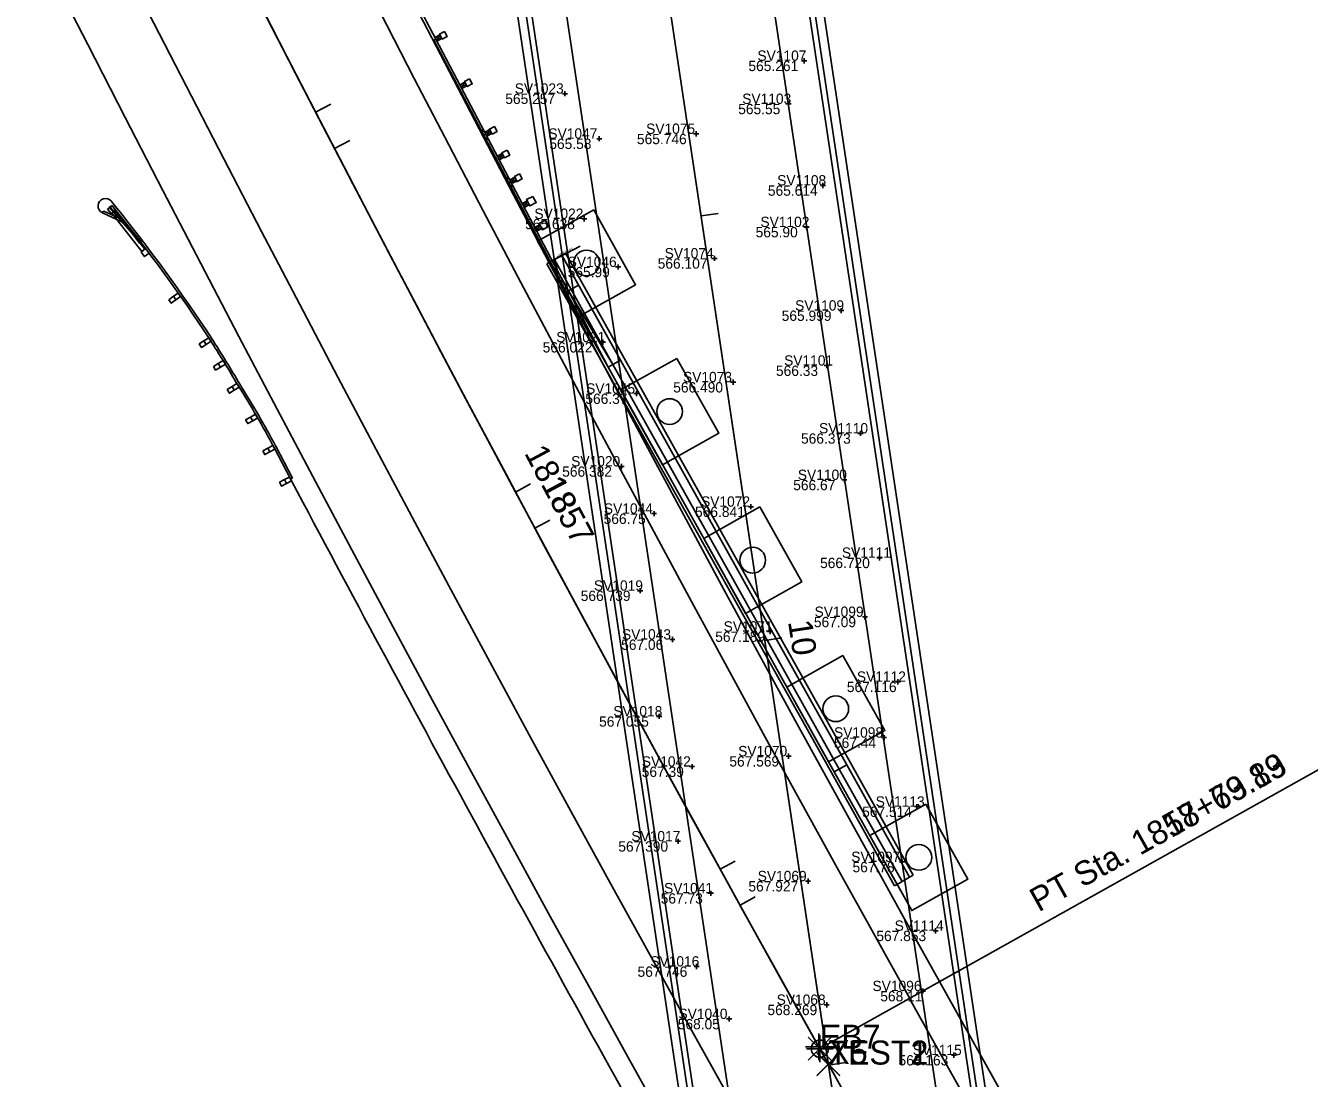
# Model space of a CAD drawing. Extents: x 6334 to 41599, y 9030 to 59113.
# Drawn here: x 21027.9 to 21177.4, y 34361.6 to 34484.2 of the extents above; entities that cross this region are included whole.
import ezdxf

# ---------------------------------------------------------------- set-up
doc = ezdxf.new("R2010")
doc.units = 0
for name, color, linetype in [('BR_X_Slab_Centerline', 7, 'Continuous'), ('BR_X_SV_Deck_Top', 7, 'Continuous'), ('BR_X_SV_Deck_Top_Text', 7, 'Continuous'), ('BR_X_SV_Pier', 7, 'Continuous'), ('GE_P_CL_20', 7, 'Continuous'), ('GE_X_CL_20', 7, 'Continuous'), ('GK_Visualization', 7, 'Continuous'), ('PM_X_CL_Double_Solid', 7, 'Continuous'), ('PM_X_Lane_Line', 7, 'Continuous'), ('PV_X_EOP', 7, 'Continuous'), ('PV_X_Shoulder', 7, 'Continuous'), ('RD_P_Concrete_Barrier', 7, 'Continuous'), ('RD_P_GR_Lt_Replaced', 7, 'Continuous'), ('RD_P_GR_Rt_Replaced', 7, 'Continuous'), ('SV_X_Shot_Marker', 7, 'Continuous'), ('SV_X_Text_Elevation', 7, 'Continuous'), ('SV_X_Text_Name', 7, 'Continuous')]:
    doc.layers.add(name, color=color, linetype=linetype)

msp = doc.modelspace()

# ---------------------------------------------------------------- linework, layer by layer
at = {"layer": 'BR_X_Slab_Centerline'}
msp.add_line((21088.12, 34584.84), (21156.74, 34127.95), dxfattribs=at)
at = {"layer": 'BR_X_SV_Deck_Top'}
for p, q in [((21072.33, 34570.99), (21124.14, 34226.08)), ((21073.52, 34569.83), (21125.21, 34225.67)), ((21074.44, 34568.18), (21126.13, 34224.03)), ((21118.68, 34489.07), (21170.37, 34144.92)), ((21119.6, 34487.43), (21171.29, 34143.27)), ((21120.67, 34487.02), (21172.48, 34142.11))]:
    msp.add_line(p, q, dxfattribs=at)
at = {"layer": 'BR_X_SV_Deck_Top_Text'}
for p, q in [((21118.87, 34480.12), (21118.27, 34480.12)), ((21118.57, 34480.42), (21118.57, 34479.82)), ((21090.7, 34476.59), (21090.7, 34475.99)), ((21091, 34476.29), (21090.4, 34476.29)), ((21120.77, 34465.9), (21120.77, 34465.3)), ((21121.07, 34465.6), (21120.47, 34465.6)), ((21093.26, 34461.71), (21092.66, 34461.71)), ((21092.96, 34462.01), (21092.96, 34461.41)), ((21123.2, 34451.03), (21122.6, 34451.03)), ((21122.9, 34451.33), (21122.9, 34450.73)), ((21095.41, 34447.35), (21094.81, 34447.35)), ((21095.11, 34447.65), (21095.11, 34447.05)), ((21125.44, 34436.73), (21124.84, 34436.73)), ((21125.14, 34437.03), (21125.14, 34436.43)), ((21097.3, 34433.18), (21097.3, 34432.58)), ((21097.6, 34432.88), (21097, 34432.88)), ((21127.35, 34422.54), (21127.35, 34421.94)), ((21127.65, 34422.24), (21127.05, 34422.24)), ((21099.76, 34418.41), (21099.16, 34418.41)), ((21099.46, 34418.71), (21099.46, 34418.11)), ((21129.8, 34407.8), (21129.2, 34407.8)), ((21129.5, 34408.1), (21129.5, 34407.5)), ((21101.98, 34403.77), (21101.38, 34403.77)), ((21101.68, 34404.07), (21101.68, 34403.47)), ((21132.02, 34393.26), (21131.42, 34393.26)), ((21131.72, 34393.56), (21131.72, 34392.96)), ((21104.18, 34389.22), (21103.58, 34389.22)), ((21103.88, 34389.52), (21103.88, 34388.92)), ((21134.19, 34378.8), (21133.59, 34378.8)), ((21133.89, 34379.1), (21133.89, 34378.5)), ((21106.34, 34374.64), (21105.74, 34374.64)), ((21106.04, 34374.94), (21106.04, 34374.34)), ((21136.33, 34364.32), (21135.73, 34364.32)), ((21136.03, 34364.62), (21136.03, 34364.02))]:
    msp.add_line(p, q, dxfattribs=at)
at = {"layer": 'BR_X_SV_Pier'}
for points in [[(21094.06, 34462.77), (21098.94, 34454.04), (21092.39, 34450.38), (21087.51, 34459.11)], [(21103.73, 34445.46), (21108.62, 34436.74), (21102.07, 34433.07), (21097.19, 34441.8)], [(21113.41, 34428.16), (21118.29, 34419.43), (21111.75, 34415.77), (21106.87, 34424.5)], [(21123.09, 34410.85), (21127.97, 34402.12), (21121.43, 34398.46), (21116.55, 34407.19)], [(21132.77, 34393.55), (21137.65, 34384.82), (21131.11, 34381.16), (21126.22, 34389.89)]]:
    msp.add_lwpolyline(points, close=True, dxfattribs=at)
for centre in [(21093.22, 34456.57), (21102.9, 34439.27), (21112.58, 34421.96), (21122.26, 34404.66), (21131.94, 34387.35)]:
    msp.add_circle(centre, 1.5, dxfattribs=at)
at = {"layer": 'GE_P_CL_20'}
for p, q in [((21106.56, 34462.05), (21108.54, 34462.35)), ((21113.99, 34412.61), (21115.96, 34412.9)), ((21121.41, 34363.16), (21123.39, 34363.46))]:
    msp.add_line(p, q, dxfattribs=at)
at = {"layer": 'GE_X_CL_20'}
for p, q in [((21061.65, 34474.14), (21063.42, 34475.06)), ((21063.84, 34469.91), (21065.62, 34470.83)), ((21084.94, 34429.9), (21086.7, 34430.84)), ((21087.19, 34425.7), (21088.95, 34426.64)), ((21121.27, 34365.55), (21182.37, 34399.72)), ((21121.27, 34365.55), (21182.3, 34399.68)), ((21108.8, 34385.96), (21110.55, 34386.92)), ((21111.1, 34381.78), (21112.85, 34382.75)), ((21120.4, 34365.07), (21585.88, 33532.76))]:
    msp.add_line(p, q, dxfattribs=at)
for centre in [(21120.4, 34365.07), (21120.4, 34365.06)]:
    msp.add_circle(centre, 1, dxfattribs=at)
msp.add_arc((24529.94, 36271.9), 3906.53, 186.21667, 209.21667, dxfattribs=at)
at = {"layer": 'GK_Visualization'}
for p, q in [((21084.27, 34610.45), (21262.51, 33423.7)), ((21084.27, 34610.45), (21262.51, 33423.7)), ((21119.06, 34363.73), (21121.73, 34366.4)), ((21119.06, 34366.4), (21121.73, 34363.73)), ((21120.28, 34366.84), (21120.28, 34363.72)), ((21120.4, 34366.63), (21120.4, 34363.51)), ((21121.84, 34365.28), (21118.72, 34365.28)), ((21121.96, 34365.07), (21118.84, 34365.07)), ((21120.06, 34361.95), (21122.73, 34364.62)), ((21120.06, 34364.62), (21122.73, 34361.95)), ((21120.07, 34361.89), (21122.74, 34364.56)), ((21120.07, 34364.56), (21122.74, 34361.89)), ((21120.07, 34361.89), (21122.74, 34364.56)), ((21120.07, 34364.56), (21122.74, 34361.89)), ((21120.28, 34365.28), (21585.88, 33532.76)), ((21120.4, 34365.07), (21585.88, 33532.76))]:
    msp.add_line(p, q, dxfattribs=at)
for centre, start, end in [((24529.91, 36271.94), 186.21497, 209.2138), ((24529.91, 36271.94), 186.21497, 209.2138), ((24529.94, 36271.9), 186.21667, 209.21667), ((24529.94, 36271.9), 186.21667, 209.21667)]:
    msp.add_arc(centre, 3906.53, start, end, dxfattribs=at)
at = {"layer": 'PM_X_CL_Double_Solid'}
msp.add_line((21084.27, 34610.45), (21262.51, 33423.7), dxfattribs=at)
at = {"layer": 'PM_X_Lane_Line'}
msp.add_line((21120.4, 34365.07), (21585.88, 33532.76), dxfattribs=at)
msp.add_line((21120.4, 34365.07), (21585.88, 33532.76), dxfattribs=at)
for start in [186.21667, 191.33607]:
    msp.add_arc((24529.94, 36271.9), 3906.53, start, 209.21667, dxfattribs=at)
at = {"layer": 'PV_X_EOP'}
for p, q in [((21096.14, 34612.23), (21274.38, 33425.48)), ((21072.4, 34608.67), (21250.65, 33421.92)), ((21130.87, 34370.92), (21596.35, 33538.62))]:
    msp.add_line(p, q, dxfattribs=at)
for centre, radius, start, end in [((24529.94, 36271.9), 3918.53, 191.33607, 209.21667), ((24531.79, 36272.61), 3896.49, 192.87045, 209.21252)]:
    msp.add_arc(centre, radius, start, end, dxfattribs=at)
at = {"layer": 'PV_X_Shoulder'}
msp.add_line((21134.36, 34372.88), (21599.84, 33540.57), dxfattribs=at)
for radius, start in [(3926.53, 191.34141), (3890.53, 192.86631)]:
    msp.add_arc((24529.94, 36271.9), radius, start, 209.21667, dxfattribs=at)
at = {"layer": 'RD_P_Concrete_Barrier'}
for p, q in [((21088.88, 34456.65), (21090.34, 34457.47)), ((21096.3, 34444.76), (21089.47, 34456.98)), ((21089.47, 34456.98), (21089.82, 34455.67)), ((21090.34, 34457.47), (21090.78, 34457.71)), ((21097.17, 34445.25), (21090.34, 34457.47)), ((21097.61, 34445.49), (21090.78, 34457.71)), ((21088.88, 34456.65), (21088.6, 34456.49)), ((21095.43, 34444.27), (21088.6, 34456.49)), ((21095.72, 34444.43), (21088.88, 34456.65)), ((21091.13, 34453.33), (21089.82, 34455.67)), ((21090.84, 34453.16), (21092.29, 34453.98)), ((21091.13, 34453.33), (21095.72, 34444.43)), ((21096.3, 34444.76), (21091.13, 34453.33)), ((21095.72, 34444.43), (21097.17, 34445.25)), ((21113.85, 34415.43), (21097.17, 34445.25)), ((21114.28, 34415.68), (21097.61, 34445.49)), ((21112.1, 34414.46), (21095.43, 34444.27)), ((21112.39, 34414.62), (21095.72, 34444.43)), ((21112.98, 34414.95), (21096.3, 34444.76)), ((21123.53, 34398.12), (21113.85, 34415.43)), ((21123.97, 34398.36), (21114.28, 34415.68)), ((21121.79, 34397.14), (21112.1, 34414.46)), ((21122.08, 34397.3), (21112.39, 34414.62)), ((21122.66, 34397.63), (21112.98, 34414.95)), ((21129.11, 34384.05), (21121.79, 34397.14)), ((21122.08, 34397.3), (21123.53, 34398.12)), ((21129.4, 34384.21), (21122.08, 34397.3)), ((21129.98, 34384.54), (21122.66, 34397.63)), ((21130.85, 34385.03), (21123.53, 34398.12)), ((21131.29, 34385.27), (21123.97, 34398.36)), ((21130.85, 34385.03), (21131.29, 34385.27)), ((21129.4, 34384.21), (21129.11, 34384.05)), ((21129.4, 34384.21), (21130.85, 34385.03))]:
    msp.add_line(p, q, dxfattribs=at)
at = {"layer": 'RD_P_GR_Lt_Replaced'}
msp.add_arc((24528.37, 36271.33), 3888.53, 206.28223, 207.38668, dxfattribs=at)
at = {"layer": 'RD_P_GR_Rt_Replaced'}
for p, q in [((21075.43, 34482.52), (21075.65, 34482.63)), ((21090.49, 34453.86), (21075.43, 34482.52)), ((21075.54, 34482.85), (21076.36, 34482.72)), ((21091.07, 34453.29), (21075.65, 34482.63)), ((21076.13, 34483.16), (21075.77, 34482.41)), ((21079.27, 34477.19), (21078.44, 34477.32)), ((21079.03, 34477.63), (21078.68, 34476.88)), ((21080.97, 34471.98), (21081.19, 34472.1)), ((21081.94, 34472.1), (21081.58, 34471.35)), ((21081.25, 34471.45), (21081.47, 34471.57)), ((21082.17, 34471.66), (21081.35, 34471.79)), ((21081.53, 34470.92), (21081.75, 34471.04)), ((21083.63, 34468.89), (21082.81, 34469.02)), ((21083.4, 34469.33), (21083.04, 34468.58)), ((21083.87, 34466.45), (21084.1, 34466.57)), ((21084.15, 34465.92), (21084.37, 34466.03)), ((21085.08, 34466.12), (21084.26, 34466.26)), ((21084.85, 34466.57), (21084.49, 34465.81)), ((21084.43, 34465.39), (21084.65, 34465.5)), ((21037.6, 34463.08), (21037.65, 34463.13)), ((21037.6, 34463.08), (21041.26, 34458.9)), ((21037.65, 34463.13), (21041.32, 34458.95)), ((21037.85, 34463.75), (21038.33, 34463.16)), ((21086.53, 34463.36), (21085.71, 34463.49)), ((21086.3, 34463.8), (21085.94, 34463.05)), ((21036.97, 34462.61), (21036.74, 34462.45)), ((21036.81, 34462.41), (21039.64, 34461.11)), ((21036.97, 34462.61), (21039.3, 34461.54)), ((21041.39, 34457.91), (21037.9, 34462.39)), ((21041.76, 34458.19), (21038.26, 34462.68)), ((21087.99, 34460.59), (21087.17, 34460.72)), ((21087.76, 34461.03), (21087.4, 34460.28)), ((21041.26, 34458.9), (21041.32, 34458.95)), ((21089.21, 34456.83), (21092.47, 34458.54)), ((21089.69, 34455.38), (21089.91, 34455.5)), ((21089.97, 34454.85), (21090.19, 34454.97)), ((21090.25, 34454.32), (21090.47, 34454.44)), ((21091.04, 34453.27), (21090.92, 34453.5)), ((21091.04, 34453.27), (21091.07, 34453.29)), ((21058.74, 34431.42), (21056.8, 34435.1)), ((21058.96, 34431.53), (21057.02, 34435.22)), ((21058.96, 34431.53), (21058.74, 34431.42))]:
    msp.add_line(p, q, dxfattribs=at)
for points in [[(21076.13, 34483.16), (21076.36, 34482.72), (21075.77, 34482.41), (21075.54, 34482.85)], [(21076.68, 34483.54), (21076.99, 34482.95), (21076.4, 34482.64), (21076.09, 34483.23)], [(21079.59, 34478.02), (21079.9, 34477.43), (21079.31, 34477.12), (21079, 34477.71)], [(21079.03, 34477.63), (21079.27, 34477.19), (21078.68, 34476.88), (21078.44, 34477.32)], [(21081.94, 34472.1), (21082.17, 34471.66), (21081.58, 34471.35), (21081.35, 34471.79)], [(21082.49, 34472.48), (21082.8, 34471.89), (21082.21, 34471.58), (21081.9, 34472.17)], [(21083.4, 34469.33), (21083.63, 34468.89), (21083.04, 34468.58), (21082.81, 34469.02)], [(21083.95, 34469.72), (21084.26, 34469.13), (21083.67, 34468.82), (21083.36, 34469.41)], [(21084.85, 34466.57), (21085.08, 34466.12), (21084.49, 34465.81), (21084.26, 34466.26)], [(21085.4, 34466.95), (21085.71, 34466.36), (21085.12, 34466.05), (21084.81, 34466.64)], [(21037.41, 34462.85), (21037.82, 34462.33), (21038.34, 34462.74), (21037.93, 34463.26)], [(21086.3, 34463.8), (21086.53, 34463.36), (21085.94, 34463.05), (21085.71, 34463.49)], [(21086.96, 34464.33), (21087.35, 34463.6), (21086.61, 34463.21), (21086.22, 34463.95)], [(21088.42, 34461.57), (21088.8, 34460.83), (21088.07, 34460.44), (21087.68, 34461.18)], [(21039.86, 34460.59), (21039.98, 34460.69), (21040.43, 34460.12), (21040.32, 34460.02)], [(21040.3, 34459.96), (21040.48, 34460.09), (21041.32, 34459.02), (21041.14, 34458.88)], [(21087.76, 34461.03), (21087.99, 34460.59), (21087.4, 34460.28), (21087.17, 34460.72)], [(21041.31, 34457.85), (21041.71, 34457.32), (21042.24, 34457.72), (21041.84, 34458.25)], [(21044.54, 34452.3), (21044.83, 34451.89), (21045.37, 34452.28), (21045.09, 34452.69)], [(21045.09, 34452.69), (21045.37, 34452.28), (21045.92, 34452.66), (21045.63, 34453.07)], [(21048.07, 34447.15), (21048.34, 34446.73), (21048.9, 34447.09), (21048.63, 34447.51)], [(21048.63, 34447.51), (21048.9, 34447.09), (21049.46, 34447.45), (21049.19, 34447.87)], [(21050.3, 34444.87), (21050.56, 34444.45), (21051.13, 34444.79), (21050.86, 34445.22)], [(21049.73, 34444.52), (21049.99, 34444.1), (21050.56, 34444.45), (21050.3, 34444.87)], [(21051.34, 34441.84), (21051.6, 34441.41), (21052.17, 34441.76), (21051.91, 34442.19)], [(21051.91, 34442.19), (21052.17, 34441.76), (21052.74, 34442.11), (21052.48, 34442.54)], [(21054.07, 34438.63), (21054.32, 34438.2), (21054.9, 34438.53), (21054.65, 34438.96)], [(21053.49, 34438.3), (21053.74, 34437.86), (21054.32, 34438.2), (21054.07, 34438.63)], [(21055.5, 34434.7), (21055.73, 34434.26), (21056.32, 34434.57), (21056.09, 34435.02)], [(21056.09, 34435.02), (21056.32, 34434.57), (21056.91, 34434.88), (21056.68, 34435.33)], [(21058.03, 34431.34), (21058.25, 34430.89), (21058.85, 34431.19), (21058.62, 34431.64)], [(21057.43, 34431.03), (21057.66, 34430.59), (21058.25, 34430.89), (21058.03, 34431.34)]]:
    msp.add_lwpolyline(points, close=True, dxfattribs=at)
for centre, radius, start, end in [((21037.17, 34463.21), 0.875, 38.7132, 245.2831), ((20880.33, 34336.14), 202.48, 33.4232, 38.7985), ((20880.33, 34336.14), 202.73, 33.4232, 38.7985), ((21091.11, 34454.15), 0.684, 205.7655, 254.5082), ((20911.01, 34358.91), 164.34, 30.5014, 32.6875), ((20911.01, 34358.91), 164.59, 30.5014, 32.6875), ((20954.16, 34380.4), 116.3, 28.055, 32.1675), ((20954.16, 34380.4), 116.55, 28.055, 32.1675), ((24529.93, 36271.95), 3928.97, 207.9175, 209.21019)]:
    msp.add_arc(centre, radius, start, end, dxfattribs=at)
for centre in [(21081.14, 34471.92), (21081.58, 34471.08), (21084.05, 34466.38), (21084.49, 34465.54), (21089.86, 34455.32), (21090.3, 34454.48)]:
    msp.add_ellipse(centre, major_axis=(0.0176, -0.0335), ratio=0.460352, dxfattribs=at)
at = {"layer": 'SV_X_Shot_Marker'}
for p, q in [((21117.05, 34475.1), (21116.45, 34475.1)), ((21116.75, 34475.4), (21116.75, 34474.8)), ((21106, 34471.91), (21106, 34471.31)), ((21095, 34471.05), (21094.4, 34471.05)), ((21094.7, 34471.35), (21094.7, 34470.75)), ((21106.3, 34471.61), (21105.7, 34471.61)), ((21119.14, 34460.76), (21118.54, 34460.76)), ((21118.84, 34461.06), (21118.84, 34460.46)), ((21108.43, 34457.11), (21107.83, 34457.11)), ((21108.13, 34457.41), (21108.13, 34456.81)), ((21097.2, 34456.11), (21096.6, 34456.11)), ((21096.9, 34456.41), (21096.9, 34455.81)), ((21121.5, 34444.62), (21120.9, 34444.62)), ((21121.2, 34444.92), (21121.2, 34444.32)), ((21110.61, 34442.69), (21110.01, 34442.69)), ((21110.31, 34442.99), (21110.31, 34442.39)), ((21099.34, 34441.36), (21098.74, 34441.36)), ((21099.04, 34441.66), (21099.04, 34441.06)), ((21123.26, 34431.61), (21123.26, 34431.01)), ((21123.56, 34431.31), (21122.96, 34431.31)), ((21112.38, 34428.49), (21112.38, 34427.89)), ((21101.38, 34427.38), (21100.78, 34427.38)), ((21101.08, 34427.68), (21101.08, 34427.08)), ((21112.68, 34428.19), (21112.08, 34428.19)), ((21125.96, 34415.36), (21125.36, 34415.36)), ((21125.66, 34415.66), (21125.66, 34415.06)), ((21114.91, 34413.65), (21114.31, 34413.65)), ((21114.61, 34413.95), (21114.61, 34413.35)), ((21103.52, 34412.72), (21102.92, 34412.72)), ((21103.22, 34413.02), (21103.22, 34412.42)), ((21127.88, 34401.6), (21127.88, 34401)), ((21128.18, 34401.3), (21127.58, 34401.3)), ((21117.06, 34399.13), (21116.46, 34399.13)), ((21116.76, 34399.43), (21116.76, 34398.83)), ((21105.81, 34397.92), (21105.21, 34397.92)), ((21105.51, 34398.22), (21105.51, 34397.62)), ((21130.29, 34386.82), (21129.69, 34386.82)), ((21129.99, 34387.12), (21129.99, 34386.52)), ((21119.33, 34384.58), (21118.73, 34384.58)), ((21119.03, 34384.88), (21119.03, 34384.28)), ((21108, 34383.17), (21107.4, 34383.17)), ((21107.7, 34383.47), (21107.7, 34382.87)), ((21132.72, 34371.78), (21132.12, 34371.78)), ((21132.42, 34372.08), (21132.42, 34371.48)), ((21121.5, 34370.18), (21120.9, 34370.18)), ((21121.2, 34370.48), (21121.2, 34369.88)), ((21109.83, 34368.83), (21109.83, 34368.23)), ((21110.13, 34368.53), (21109.53, 34368.53))]:
    msp.add_line(p, q, dxfattribs=at)

# ---------------------------------------------------------------- texts
at = {"layer": 'BR_X_SV_Deck_Top_Text'}
for s, p in [('SV1107', (21113.13, 34480.12)), ('565.261', (21112.08, 34478.92)), ('SV1023', (21084.85, 34476.29)), ('565.257', (21083.75, 34475.09)), ('SV1108', (21115.43, 34465.6)), ('565.614', (21114.35, 34464.4)), ('SV1022', (21087.14, 34461.71)), ('565.638', (21086.06, 34460.51)), ('565.999', (21115.96, 34449.83)), ('SV1109', (21117.52, 34451.03)), ('SV1021', (21089.69, 34447.35)), ('566.022', (21088.11, 34446.15)), ('SV1110', (21120.31, 34436.73)), ('566.373', (21118.21, 34435.53)), ('SV1020', (21091.43, 34432.88)), ('566.382', (21090.38, 34431.68)), ('SV1111', (21122.97, 34422.24)), ('566.720', (21120.43, 34421.04)), ('SV1019', (21094.08, 34418.41)), ('566.739', (21092.54, 34417.21)), ('567.116', (21123.55, 34406.6)), ('SV1112', (21124.72, 34407.8)), ('SV1018', (21096.34, 34403.77)), ('567.055', (21094.68, 34402.57)), ('SV1113', (21126.91, 34393.26)), ('567.514', (21125.33, 34392.06)), ('SV1017', (21098.44, 34389.22)), ('567.390', (21096.92, 34388.02)), ('SV1114', (21129.12, 34378.8)), ('567.853', (21126.99, 34377.6)), ('567.746', (21099.16, 34373.44)), ('SV1016', (21100.65, 34374.64)), ('568.163', (21129.57, 34363.12)), ('SV1115', (21131.23, 34364.32))]:
    msp.add_text(s, height=1.2, dxfattribs=at).set_placement(p)
at = {"layer": 'GE_P_CL_20'}
msp.add_text('10', height=2.8, rotation=278.5417, dxfattribs=at).set_placement((21116.69, 34414.81))
at = {"layer": 'GE_X_CL_20'}
for s, rotation, p in [('1818', 298.1329, (21085.91, 34434.44)), ('1857', 298.2027, (21087.84, 34430.83)), ('PT Sta. 1818+73.89', 29.2167, (21145.9, 34380.93)), ('PT Sta. 1857+69.13', 29.2167, (21145.9, 34380.93))]:
    msp.add_text(s, height=2.8, rotation=rotation, dxfattribs=at).set_placement(p)
at = {"layer": 'GK_Visualization'}
for s, p in [('EB7', (21120.4, 34365.07)), ('X5', (21121.39, 34363.28)), ('TEST1', (21121.4, 34363.22)), ('TEST2', (21121.4, 34363.22))]:
    msp.add_text(s, height=2.8, dxfattribs=at).set_placement(p)
at = {"layer": 'RD_P_GR_Rt_Replaced'}
msp.add_text('end of barrier', height=0.25, rotation=27.7167, dxfattribs=at).set_placement((21089.83, 34457.25))
at = {"layer": 'SV_X_Text_Elevation'}
for s, p in [('565.55', (21110.89, 34473.9)), ('565.58', (21088.88, 34469.85)), ('565.746', (21099.09, 34470.41)), ('565.90', (21112.92, 34459.56)), ('566.107', (21101.51, 34455.91)), ('565.99', (21091.02, 34454.91)), ('566.33', (21115.29, 34443.42)), ('566.490', (21103.32, 34441.49)), ('566.37', (21093.08, 34440.16)), ('566.67', (21117.3, 34430.11)), ('566.75', (21095.21, 34426.18)), ('566.841', (21105.86, 34426.99)), ('567.09', (21119.71, 34414.16)), ('567.189', (21108.21, 34412.45)), ('567.06', (21097.25, 34411.52)), ('567.44', (21122.05, 34400.1)), ('567.569', (21109.86, 34397.93)), ('567.39', (21099.65, 34396.72)), ('567.78', (21124.21, 34385.62)), ('567.927', (21112.08, 34383.38)), ('567.73', (21101.86, 34381.97)), ('568.11', (21127.45, 34370.58)), ('568.269', (21114.3, 34368.98)), ('568.05', (21103.85, 34367.33))]:
    msp.add_text(s, height=1.2, dxfattribs=at).set_placement(p)
at = {"layer": 'SV_X_Text_Name'}
for s, p in [('SV1103', (21111.36, 34475.1)), ('SV1047', (21088.77, 34471.05)), ('SV1075', (21100.16, 34471.61)), ('SV1102', (21113.48, 34460.76)), ('SV1046', (21091.02, 34456.11)), ('SV1074', (21102.32, 34457.11)), ('SV1101', (21116.24, 34444.62)), ('SV1073', (21104.46, 34442.69)), ('SV1045', (21093.17, 34441.36)), ('SV1100', (21117.84, 34431.31)), ('SV1044', (21095.24, 34427.38)), ('SV1072', (21106.56, 34428.19)), ('SV1099', (21119.79, 34415.36)), ('SV1043', (21097.35, 34412.72)), ('SV1071', (21109.19, 34413.65)), ('SV1098', (21122.06, 34401.3)), ('SV1070', (21110.89, 34399.13)), ('SV1042', (21099.66, 34397.92)), ('SV1097', (21124.06, 34386.82)), ('SV1069', (21113.16, 34384.58)), ('SV1041', (21102.25, 34383.17)), ('SV1096', (21126.54, 34371.78)), ('SV1068', (21115.37, 34370.18)), ('SV1040', (21103.93, 34368.53))]:
    msp.add_text(s, height=1.2, dxfattribs=at).set_placement(p)

doc.saveas('drawing.dxf')
